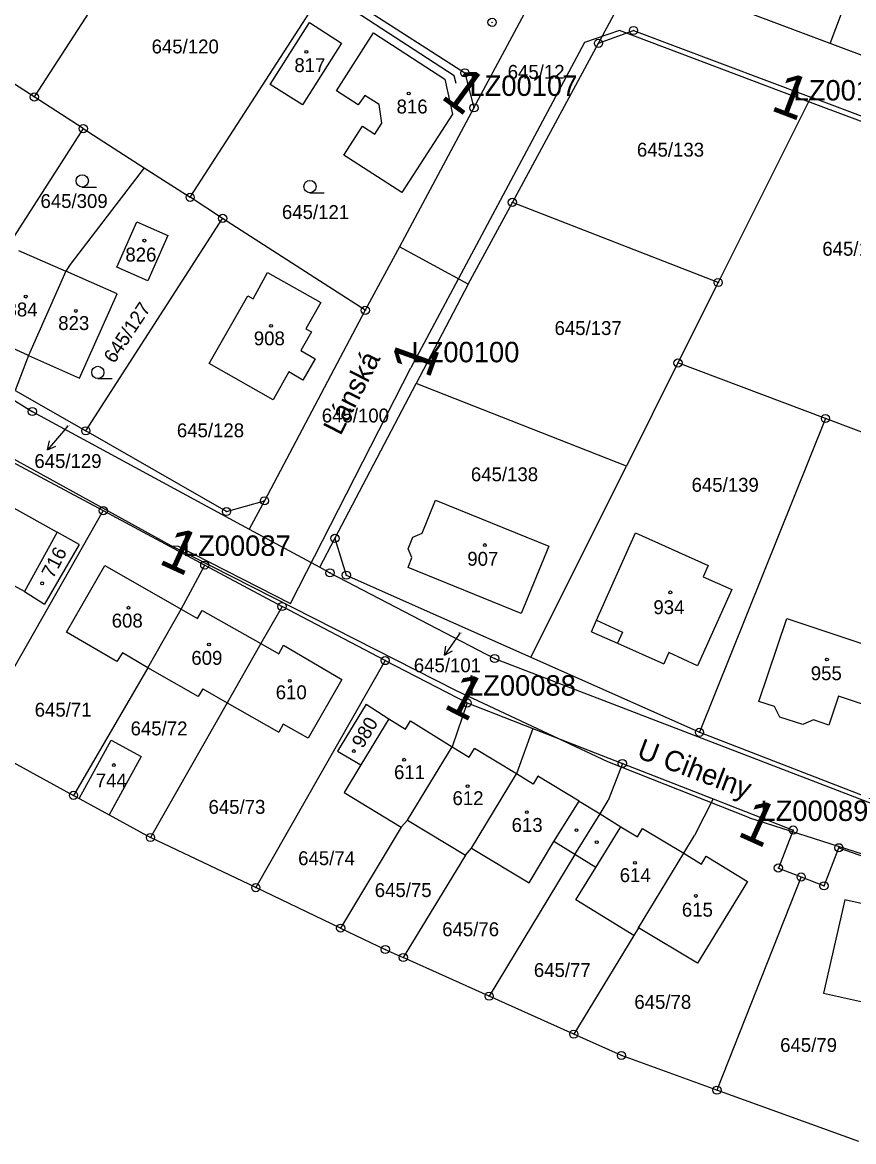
# Model space of a CAD drawing. Extents: x -738131 to -734179, y -1033447 to -1030078.
# Drawn here: x -736106 to -736004.3, y -1032949.2 to -1032812.2 of the extents above; entities that cross this region are included whole.
import ezdxf

# ---------------------------------------------------------------- set-up
doc = ezdxf.new("R2010")
doc.units = 0
for name, color, linetype in [('ftf_2010', 7, 'Continuous'), ('ftf_3010', 7, 'Continuous'), ('ftf_3010_ftf_3010_gtda_3015_gtda_3015_1', 7, 'Continuous'), ('ftf_nu', 7, 'Continuous'), ('Vrstva 1', 7, 'Continuous'), ('Vrstva 2', 7, 'Continuous'), ('Vrstva 3', 7, 'Continuous'), ('Vrstva 4', 7, 'Continuous'), ('Vrstva 5', 7, 'Continuous'), ('Vrstva 7', 7, 'Continuous'), ('Vrstva 8', 7, 'Continuous')]:
    doc.layers.add(name, color=color, linetype=linetype)

msp = doc.modelspace()

# ---------------------------------------------------------------- linework, layer by layer
at = {"layer": 'ftf_2010'}
for points in [[(-736052.9, -1032819.73), (-736053.14, -1032818.79), (-736087.84, -1032796.17)], [(-736013.08, -1032820.73), (-736032.92, -1032813.21), (-736037.22, -1032814.71), (-736058.45, -1032854.48)], [(-735967.72, -1032837.65), (-736013.08, -1032820.73)], [(-736087.78, -1032876.29), (-736086.92, -1032876.31), (-736073.17, -1032883.33), (-736058.45, -1032854.48)], [(-736087.78, -1032876.29), (-736124.23, -1032856.21)], [(-736052.87, -1032894.01), (-736087.78, -1032876.29)], [(-736017.04, -1032909.56), (-736034.36, -1032902.68), (-736052.87, -1032894.01)], [(-736017.04, -1032909.56), (-735980.57, -1032921.21)]]:
    msp.add_lwpolyline(points, dxfattribs=at)
at = {"layer": 'Vrstva 1'}
for points in [[(-736007.17, -1032814.81), (-735995.73, -1032784.44)], [(-736087.69, -1032795.31), (-736104.51, -1032821.36)], [(-736035.51, -1032814.79), (-736029.29, -1032803.29)], [(-736007.17, -1032814.81), (-736027.92, -1032806.99)], [(-736085.44, -1032833.63), (-736068.65, -1032807.58)], [(-736068.65, -1032807.58), (-736051.85, -1032818.41)], [(-736050.74, -1032822.69), (-736044.6, -1032811.22)], [(-736075.67, -1032819.82), (-736070.87, -1032812.24)], [(-736070.87, -1032812.24), (-736066.93, -1032814.79)], [(-736104.51, -1032821.36), (-736115.57, -1032814.24)], [(-736067.55, -1032820.59), (-736063.01, -1032813.53)], [(-736063.01, -1032813.53), (-736054.3, -1032819.17)], [(-736035.51, -1032814.79), (-736031.23, -1032813.23)], [(-736031.23, -1032813.23), (-736009.52, -1032821.4)], [(-736066.93, -1032814.79), (-736071.72, -1032822.32)], [(-736046.04, -1032834.25), (-736035.51, -1032814.79)], [(-735975.92, -1032826.57), (-736007.17, -1032814.81)], [(-736051.85, -1032818.41), (-736050.74, -1032822.69)], [(-736054.3, -1032819.17), (-736053.38, -1032823.45)], [(-736071.72, -1032822.32), (-736075.67, -1032819.82)], [(-736064.88, -1032822.33), (-736067.55, -1032820.59)], [(-736064.1, -1032821.16), (-736064.88, -1032822.33)], [(-736062.35, -1032822.29), (-736064.1, -1032821.16)], [(-736098.52, -1032825.23), (-736104.51, -1032821.36)], [(-736062.01, -1032824.55), (-736062.35, -1032822.29)], [(-736009.52, -1032821.4), (-736020.87, -1032844.06)], [(-735987.42, -1032829.72), (-736009.52, -1032821.4)], [(-736050.74, -1032822.69), (-736059.86, -1032839.69)], [(-736053.38, -1032823.45), (-736059.57, -1032833.03)], [(-736098.52, -1032825.23), (-736115.82, -1032852.13)], [(-736098.52, -1032825.23), (-736091.08, -1032830.01)], [(-736066.64, -1032828.49), (-736064.36, -1032824.93)], [(-736064.36, -1032824.93), (-736062.84, -1032825.91)], [(-736062.84, -1032825.91), (-736062.01, -1032824.55)], [(-736059.57, -1032833.03), (-736066.64, -1032828.49)], [(-736091.08, -1032830.01), (-736100.12, -1032841.87)], [(-736091.08, -1032830.01), (-736085.44, -1032833.63)], [(-736081.47, -1032836.21), (-736085.44, -1032833.63)], [(-736051.45, -1032844.26), (-736046.04, -1032834.25)], [(-736020.87, -1032844.06), (-736046.04, -1032834.25)], [(-736098.21, -1032862.2), (-736081.47, -1032836.21)], [(-736064.03, -1032847.46), (-736081.47, -1032836.21)], [(-736094.4, -1032842.18), (-736091.96, -1032836.65)], [(-736091.96, -1032836.65), (-736088.16, -1032838.32)], [(-736088.16, -1032838.32), (-736090.61, -1032843.84)], [(-736106.46, -1032840.13), (-736100.64, -1032842.69)], [(-736059.86, -1032839.69), (-736064.03, -1032847.46)], [(-736051.45, -1032844.26), (-736059.86, -1032839.69)], [(-736100.64, -1032842.69), (-736105.21, -1032852.97)], [(-736100.12, -1032841.87), (-736100.64, -1032842.69)], [(-736094.37, -1032845.45), (-736100.64, -1032842.69)], [(-736090.61, -1032843.84), (-736094.4, -1032842.18)], [(-736077.74, -1032846.04), (-736075.98, -1032842.83)], [(-736075.98, -1032842.83), (-736069.48, -1032846.49)], [(-736051.45, -1032844.26), (-736057.82, -1032856.43)], [(-736020.87, -1032844.06), (-736025.79, -1032853.9)], [(-736098.97, -1032855.76), (-736094.37, -1032845.45)], [(-736083.12, -1032853.97), (-736078.4, -1032845.67)], [(-736078.4, -1032845.67), (-736077.74, -1032846.04)], [(-736069.48, -1032846.49), (-736071.28, -1032849.72)], [(-736064.03, -1032847.46), (-736076.36, -1032870.76)], [(-736071.28, -1032849.72), (-736070.62, -1032850.11)], [(-736105.21, -1032852.97), (-736111.05, -1032850.35)], [(-736070.62, -1032850.11), (-736071.89, -1032852.38)], [(-736071.89, -1032852.38), (-736070.16, -1032853.39)], [(-736105.21, -1032852.97), (-736106.84, -1032857.26)], [(-736105.21, -1032852.97), (-736098.97, -1032855.76)], [(-736075.29, -1032858.4), (-736083.12, -1032853.97)], [(-736070.16, -1032853.39), (-736071.65, -1032855.99)], [(-736025.79, -1032853.9), (-736032.09, -1032866.51)], [(-736007.75, -1032860.69), (-736025.79, -1032853.9)], [(-736073.38, -1032855), (-736075.29, -1032858.4)], [(-736071.65, -1032855.99), (-736073.38, -1032855)], [(-736067.74, -1032875.36), (-736057.82, -1032856.43)], [(-736032.09, -1032866.51), (-736057.82, -1032856.43)], [(-736107.91, -1032857.89), (-736104.75, -1032859.84)], [(-736106.84, -1032857.26), (-736098.21, -1032862.2)], [(-736104.75, -1032859.84), (-736078.21, -1032874.23)], [(-736007.75, -1032860.69), (-736023.16, -1032899.08)], [(-736000.15, -1032863.54), (-736007.75, -1032860.69)], [(-736081, -1032872.08), (-736098.21, -1032862.2)], [(-736108.53, -1032865.3), (-736096.07, -1032871.97)], [(-736043.8, -1032889.9), (-736032.09, -1032866.51)], [(-736110.87, -1032869.49), (-736101.71, -1032874.62)], [(-736081, -1032872.08), (-736076.36, -1032870.76)], [(-736076.36, -1032870.76), (-736078.21, -1032874.23)], [(-736057.09, -1032874.72), (-736055.42, -1032870.7)], [(-736055.42, -1032870.7), (-736041.59, -1032876.3)], [(-736096.07, -1032871.97), (-736112.08, -1032900.05)], [(-736096.07, -1032871.97), (-736083.66, -1032878.63)], [(-736078.21, -1032874.23), (-736069.59, -1032878.9)], [(-736101.71, -1032874.62), (-736105.71, -1032881.85)], [(-736099.01, -1032876.13), (-736101.71, -1032874.62)], [(-736069.59, -1032878.9), (-736067.74, -1032875.36)], [(-736067.74, -1032875.36), (-736066.35, -1032879.86)], [(-736058.79, -1032876.62), (-736058.21, -1032875.2)], [(-736058.21, -1032875.2), (-736057.09, -1032874.72)], [(-736035.77, -1032885.38), (-736030.98, -1032874.68)], [(-736030.98, -1032874.68), (-736022.1, -1032878.68)], [(-736099.01, -1032876.13), (-736103.26, -1032883.39)], [(-736058.33, -1032877.72), (-736058.79, -1032876.62)], [(-736041.59, -1032876.3), (-736044.96, -1032884.56)], [(-736086.54, -1032884.01), (-736083.66, -1032878.63)], [(-736083.66, -1032878.63), (-736074.21, -1032883.7)], [(-736058.8, -1032878.91), (-736058.33, -1032877.72)], [(-736100.56, -1032886.84), (-736095.88, -1032878.69)], [(-736095.88, -1032878.69), (-736086.54, -1032884.01)], [(-736069.59, -1032878.9), (-736068.35, -1032879.57)], [(-736068.35, -1032879.57), (-736048.21, -1032890.05)], [(-736066.35, -1032879.86), (-736043.8, -1032889.9)], [(-736044.96, -1032884.56), (-736058.8, -1032878.91)], [(-736022.1, -1032878.68), (-736022.71, -1032880.05)], [(-736105.71, -1032881.85), (-736108.69, -1032880.22)], [(-736022.71, -1032880.05), (-736019.19, -1032881.63)], [(-736105.71, -1032881.85), (-736103.26, -1032883.39)], [(-736019.19, -1032881.63), (-736023.38, -1032890.96)], [(-736090.61, -1032891.19), (-736086.54, -1032884.01)], [(-736074.21, -1032883.7), (-736076.79, -1032888.24)], [(-736061.59, -1032890.31), (-736074.21, -1032883.7)], [(-736036.37, -1032886.78), (-736035.77, -1032885.38)], [(-736015.88, -1032895.3), (-736012.46, -1032885.17)], [(-736012.46, -1032885.17), (-735998.42, -1032889.85)], [(-736094.42, -1032890.41), (-736100.56, -1032886.84)], [(-736036.37, -1032886.78), (-736033.2, -1032888.19)], [(-736076.79, -1032888.24), (-736080.9, -1032895.46)], [(-736076.79, -1032888.24), (-736074.61, -1032889.47)], [(-736033.2, -1032888.19), (-736027.53, -1032890.71)], [(-736093.72, -1032889.38), (-736094.42, -1032890.41)], [(-736090.61, -1032891.19), (-736093.72, -1032889.38)], [(-736074.61, -1032889.47), (-736074.02, -1032888.44)], [(-736074.02, -1032888.44), (-736066.91, -1032892.61)], [(-736026.9, -1032889.34), (-736027.53, -1032890.71)], [(-736023.38, -1032890.96), (-736026.9, -1032889.34)], [(-736061.59, -1032890.31), (-736077.42, -1032918.09)], [(-736061.59, -1032890.31), (-736051.57, -1032895.5)], [(-736048.21, -1032890.05), (-735998.04, -1032909.35)], [(-736043.8, -1032889.9), (-736023.16, -1032899.08)], [(-736090.61, -1032891.19), (-736099.72, -1032906.8)], [(-736084.47, -1032894.69), (-736090.61, -1032891.19)], [(-736066.91, -1032892.61), (-736071.01, -1032899.8)], [(-736083.89, -1032893.75), (-736084.47, -1032894.69)], [(-736083.89, -1032893.75), (-736080.9, -1032895.46)], [(-736006.15, -1032894.67), (-736007.32, -1032898.22)], [(-736000.64, -1032896.5), (-736006.15, -1032894.67)], [(-736080.9, -1032895.46), (-736090.29, -1032911.95)], [(-736080.9, -1032895.46), (-736074.61, -1032899.07)], [(-736063.9, -1032895.64), (-736067.41, -1032901.41)], [(-736063.9, -1032895.64), (-736061.15, -1032897.43)], [(-736051.57, -1032895.5), (-736053.4, -1032900.85)], [(-736051.57, -1032895.5), (-736043.53, -1032898.63)], [(-736013.98, -1032895.94), (-736015.88, -1032895.3)], [(-736013.33, -1032897.24), (-736013.98, -1032895.94)], [(-736061.15, -1032897.43), (-736064.56, -1032903.05)], [(-736061.15, -1032897.43), (-736059.12, -1032898.69)], [(-736059.12, -1032898.69), (-736058.48, -1032897.67)], [(-736058.48, -1032897.67), (-736053.4, -1032900.85)], [(-736010.5, -1032898.14), (-736013.33, -1032897.24)], [(-736009.22, -1032897.55), (-736010.5, -1032898.14)], [(-736007.32, -1032898.22), (-736009.22, -1032897.55)], [(-736074.09, -1032898.08), (-736074.61, -1032899.07)], [(-736071.01, -1032899.8), (-736074.09, -1032898.08)], [(-736043.53, -1032898.63), (-736045.55, -1032904.17)], [(-736043.53, -1032898.63), (-736032.58, -1032902.9)], [(-736023.16, -1032899.08), (-736001.98, -1032907.27)], [(-736112.08, -1032900.05), (-736099.72, -1032906.8)], [(-736099.02, -1032907.18), (-736095.11, -1032900.03)], [(-736095.11, -1032900.03), (-736091.45, -1032902.04)], [(-736067.41, -1032901.41), (-736064.56, -1032903.05)], [(-736058.85, -1032909.84), (-736053.4, -1032900.85)], [(-736091.45, -1032902.04), (-736095.36, -1032909.18)], [(-736064.56, -1032903.05), (-736066.63, -1032906.47)], [(-736032.58, -1032902.9), (-736034.34, -1032907.44)], [(-736032.58, -1032902.9), (-736021.48, -1032907.22)], [(-736051.02, -1032913.24), (-736045.55, -1032904.17)], [(-736099.72, -1032906.8), (-736099.02, -1032907.18)], [(-736099.02, -1032907.18), (-736095.36, -1032909.18)], [(-736066.63, -1032906.47), (-736059.62, -1032910.71)], [(-736021.48, -1032907.22), (-736023.75, -1032911.7)], [(-736021.48, -1032907.22), (-736011.7, -1032911.04)], [(-736035.32, -1032909.08), (-736034.34, -1032907.44)], [(-736095.36, -1032909.18), (-736090.29, -1032911.95)], [(-736058.85, -1032909.84), (-736059.62, -1032910.71)], [(-736058.85, -1032909.84), (-736051.78, -1032914.1)], [(-736038.4, -1032914.03), (-736035.32, -1032909.08)], [(-736059.62, -1032910.71), (-736067.04, -1032923.04)], [(-736011.7, -1032911.04), (-736013.51, -1032915.69)], [(-736077.42, -1032918.09), (-736090.29, -1032911.95)], [(-736043.98, -1032917.5), (-736040.96, -1032912.44)], [(-736038.4, -1032914.03), (-736040.96, -1032912.44)], [(-736025.08, -1032913.87), (-736023.75, -1032911.7)], [(-736051.78, -1032914.1), (-736059.38, -1032926.64)], [(-736051.78, -1032914.1), (-736051.02, -1032913.24)], [(-736051.02, -1032913.24), (-736043.98, -1032917.5)], [(-736038.4, -1032914.03), (-736048.88, -1032931.36)], [(-736035.83, -1032915.62), (-736038.4, -1032914.03)], [(-736030.6, -1032923.02), (-736025.08, -1032913.87)], [(-736025.08, -1032913.87), (-736022.91, -1032915.22)], [(-736022.91, -1032915.22), (-736022.32, -1032914.24)], [(-736022.32, -1032914.24), (-736017.27, -1032917.32)], [(-736007.92, -1032917.87), (-736006.11, -1032913.21)], [(-736006.11, -1032913.21), (-735996.2, -1032916.69)], [(-736038.29, -1032919.6), (-736035.83, -1032915.62)], [(-736010.72, -1032916.78), (-736021.02, -1032942.86)], [(-736013.51, -1032915.69), (-736010.72, -1032916.78)], [(-736010.72, -1032916.78), (-736007.92, -1032917.87)], [(-736067.04, -1032923.04), (-736077.42, -1032918.09)], [(-736017.27, -1032917.32), (-736023.4, -1032927.32)], [(-736031.19, -1032923.94), (-736038.29, -1032919.6)], [(-736005.37, -1032919.59), (-736007.98, -1032930.98)], [(-735997.35, -1032921.38), (-736005.37, -1032919.59)], [(-736067.04, -1032923.04), (-736061.58, -1032925.65)], [(-736030.6, -1032923.02), (-736031.19, -1032923.94)], [(-736023.4, -1032927.32), (-736030.6, -1032923.02)], [(-736031.19, -1032923.94), (-736038.52, -1032936.01)], [(-736061.58, -1032925.65), (-736059.38, -1032926.64)], [(-736048.88, -1032931.36), (-736059.38, -1032926.64)], [(-736038.52, -1032936.01), (-736048.88, -1032931.36)], [(-736007.98, -1032930.98), (-735999.92, -1032932.81)], [(-736032.7, -1032938.62), (-736038.52, -1032936.01)], [(-736021.02, -1032942.86), (-736032.7, -1032938.62)], [(-736003.65, -1032949.16), (-736021.02, -1032942.86)]]:
    msp.add_lwpolyline(points, dxfattribs=at)
at = {"layer": 'Vrstva 3'}
for p, q in [((-736098.64, -1032832.38), (-736096.89, -1032832.38)), ((-736070.79, -1032833.08), (-736069.04, -1032833.08)), ((-736096.74, -1032855.8), (-736094.99, -1032855.8))]:
    msp.add_line(p, q, dxfattribs=at)
for centre in [(-736098.64, -1032831.63), (-736070.79, -1032832.33), (-736096.74, -1032855.05)]:
    msp.add_circle(centre, 0.75, dxfattribs=at)
at = {"layer": 'Vrstva 4'}
for points in [[(-736086.54, -1032884.01), (-736084.53, -1032885.17)], [(-736084.53, -1032885.17), (-736083.97, -1032884.18)], [(-736083.97, -1032884.18), (-736076.79, -1032888.24)], [(-736035.77, -1032885.38), (-736032.58, -1032886.83)], [(-736032.58, -1032886.83), (-736033.2, -1032888.19)], [(-736053.4, -1032900.85), (-736051.34, -1032902.13)], [(-736051.34, -1032902.13), (-736050.67, -1032901.07)], [(-736045.55, -1032904.17), (-736050.67, -1032901.07)], [(-736043.5, -1032905.41), (-736045.55, -1032904.17)], [(-736042.91, -1032904.44), (-736043.5, -1032905.41)], [(-736037.86, -1032907.51), (-736042.91, -1032904.44)], [(-736040.96, -1032912.44), (-736037.86, -1032907.51)], [(-736037.86, -1032907.51), (-736035.32, -1032909.08)], [(-736035.32, -1032909.08), (-736032.78, -1032910.66)], [(-736035.83, -1032915.62), (-736032.78, -1032910.66)], [(-736032.78, -1032910.66), (-736030.73, -1032911.89)], [(-736030.73, -1032911.89), (-736030.11, -1032910.86)], [(-736030.11, -1032910.86), (-736025.08, -1032913.87)]]:
    msp.add_lwpolyline(points, dxfattribs=at)
at = {"layer": 'Vrstva 5'}
for centre in [(-736071.23, -1032815.84), (-736058.72, -1032820.93), (-736091.04, -1032838.93), (-736105.56, -1032845.78), (-736099.43, -1032847.54), (-736075.55, -1032849.35), (-736049.41, -1032876.18), (-736103.55, -1032880.86), (-736026.72, -1032881.97), (-736092.98, -1032883.84), (-736083.15, -1032888.34), (-736007.56, -1032890.18), (-736073.26, -1032892.79), (-736065.42, -1032901.38), (-736094.78, -1032903.09), (-736059.29, -1032902.44), (-736051.51, -1032905.68), (-736044.27, -1032908.85), (-736038.19, -1032911.05), (-736035.72, -1032912.53), (-736031.05, -1032915.05), (-736023.6, -1032919.1)]:
    msp.add_circle(centre, 0.175, dxfattribs=at)
at = {"layer": 'Vrstva 7'}
for p, q in [((-736100.95, -1032862.23), (-736102.91, -1032864.51)), ((-736102.91, -1032864.51), (-736102.63, -1032863.42)), ((-736102.91, -1032864.51), (-736101.87, -1032864.07)), ((-736052.63, -1032887.2), (-736054.35, -1032889.66)), ((-736054.35, -1032889.66), (-736054.19, -1032888.55)), ((-736054.35, -1032889.66), (-736053.37, -1032889.12))]:
    msp.add_line(p, q, dxfattribs=at)
for points in [[(-736100.41, -1032861.61), (-736100.95, -1032862.23)], [(-736052.46, -1032886.96), (-736052.63, -1032887.2)]]:
    msp.add_lwpolyline(points, dxfattribs=at)
at = {"layer": 'Vrstva 8'}
for centre, radius in [((-736048.52, -1032812.23), 0.5), ((-736048.52, -1032812.23), 0.0303), ((-736031.23, -1032813.23), 0.5), ((-736035.51, -1032814.79), 0.5), ((-736031.23, -1032813.23), 0.0303), ((-736035.51, -1032814.79), 0.0303), ((-736051.85, -1032818.41), 0.5), ((-736051.85, -1032818.41), 0.0303), ((-736104.51, -1032821.36), 0.5), ((-736104.51, -1032821.36), 0.0303), ((-736050.74, -1032822.69), 0.5), ((-736050.74, -1032822.69), 0.0303), ((-736098.52, -1032825.23), 0.5), ((-736098.52, -1032825.23), 0.0303), ((-736085.44, -1032833.63), 0.5), ((-736085.44, -1032833.63), 0.0303), ((-736046.04, -1032834.25), 0.5), ((-736046.04, -1032834.25), 0.0303), ((-736081.47, -1032836.21), 0.5), ((-736081.47, -1032836.21), 0.0303), ((-736020.87, -1032844.06), 0.5), ((-736020.87, -1032844.06), 0.0303), ((-736064.03, -1032847.46), 0.5), ((-736064.03, -1032847.46), 0.0303), ((-736025.79, -1032853.9), 0.5), ((-736025.79, -1032853.9), 0.0303), ((-736104.75, -1032859.84), 0.5), ((-736104.75, -1032859.84), 0.0303), ((-736007.75, -1032860.69), 0.5), ((-736007.75, -1032860.69), 0.0303), ((-736098.21, -1032862.2), 0.5), ((-736098.21, -1032862.2), 0.0303), ((-736076.36, -1032870.76), 0.5), ((-736096.07, -1032871.97), 0.5), ((-736081, -1032872.08), 0.5), ((-736076.36, -1032870.76), 0.0303), ((-736096.07, -1032871.97), 0.0303), ((-736081, -1032872.08), 0.0303), ((-736067.74, -1032875.36), 0.5), ((-736067.74, -1032875.36), 0.0303), ((-736083.66, -1032878.63), 0.5), ((-736083.66, -1032878.63), 0.0303), ((-736068.35, -1032879.57), 0.5), ((-736068.35, -1032879.57), 0.0303), ((-736066.35, -1032879.86), 0.5), ((-736066.35, -1032879.86), 0.0303), ((-736074.21, -1032883.7), 0.5), ((-736074.21, -1032883.7), 0.0303), ((-736048.21, -1032890.05), 0.5), ((-736061.59, -1032890.31), 0.5), ((-736061.59, -1032890.31), 0.0303), ((-736048.21, -1032890.05), 0.0303), ((-736051.57, -1032895.5), 0.5), ((-736051.57, -1032895.5), 0.0303), ((-736023.16, -1032899.08), 0.5), ((-736023.16, -1032899.08), 0.0303), ((-736032.58, -1032902.9), 0.5), ((-736032.58, -1032902.9), 0.0303), ((-736099.72, -1032906.8), 0.5), ((-736099.72, -1032906.8), 0.0303), ((-736090.29, -1032911.95), 0.5), ((-736011.7, -1032911.04), 0.5), ((-736011.7, -1032911.04), 0.0303), ((-736090.29, -1032911.95), 0.0303), ((-736006.11, -1032913.21), 0.5), ((-736006.11, -1032913.21), 0.0303), ((-736013.51, -1032915.69), 0.5), ((-736013.51, -1032915.69), 0.0303), ((-736010.72, -1032916.78), 0.5), ((-736010.72, -1032916.78), 0.0303), ((-736077.42, -1032918.09), 0.5), ((-736077.42, -1032918.09), 0.0303), ((-736007.92, -1032917.87), 0.5), ((-736007.92, -1032917.87), 0.0303), ((-736067.04, -1032923.04), 0.5), ((-736067.04, -1032923.04), 0.0303), ((-736061.58, -1032925.65), 0.5), ((-736061.58, -1032925.65), 0.0303), ((-736059.38, -1032926.64), 0.5), ((-736059.38, -1032926.64), 0.0303), ((-736048.88, -1032931.36), 0.5), ((-736048.88, -1032931.36), 0.0303), ((-736038.52, -1032936.01), 0.5), ((-736038.52, -1032936.01), 0.0303), ((-736032.7, -1032938.62), 0.5), ((-736032.7, -1032938.62), 0.0303), ((-736021.02, -1032942.86), 0.5), ((-736021.02, -1032942.86), 0.0303)]:
    msp.add_circle(centre, radius, dxfattribs=at)

# ---------------------------------------------------------------- texts
at = {"layer": 'ftf_3010'}
for rotation, p in [(323.6455, (-736054.96, -1032821.44)), (339.1572, (-736014.61, -1032822.93)), (70.2215, (-736056.22, -1032855.97)), (335.4521, (-736089.45, -1032878.38)), (333.0089, (-736054.63, -1032896.04)), (335.7622, (-736018.7, -1032911.67))]:
    msp.add_text('1', height=5.2, rotation=rotation, dxfattribs=at).set_placement(p)
at = {"layer": 'ftf_3010_ftf_3010_gtda_3015_gtda_3015_1'}
for s, p in [('LZ00107', (-736051.29, -1032821.23)), ('LZ00101', (-736011.65, -1032821.79)), ('LZ00087', (-736086.34, -1032877.5)), ('LZ00088', (-736051.47, -1032894.6)), ('LZ00089', (-736015.7, -1032909.93))]:
    msp.add_text(s, height=2.5, dxfattribs=at).set_placement(p)
msp.add_text('LZ00100', height=2.5, rotation=0, dxfattribs=at).set_placement((-736058.38, -1032853.82))
at = {"layer": 'ftf_nu'}
for s, rotation, p in [('Lánská', 62.7435, (-736067.06, -1032862.89)), ('U Cihelny', 339.213, (-736030.95, -1032902.14))]:
    msp.add_text(s, height=2.5, rotation=rotation, dxfattribs=at).set_placement(p)
at = {"layer": 'Vrstva 2'}
for s, height, p in [('645/120', 1.7, (-736090.16, -1032816.03)), ('817', 1.7, (-736072.7, -1032818.32)), ('645/12', 1.7, (-736046.61, -1032819.14)), ('816', 1.7, (-736060.2, -1032823.38)), ('645/133', 1.7, (-736030.81, -1032828.66)), ('645/309', 1.7, (-736103.75, -1032834.94)), ('645/121', 1.7, (-736074.22, -1032836.29)), ('826', 1.7, (-736093.37, -1032841.49)), ('645/134', 1.7, (-736008.13, -1032840.78)), ('884', 1.7, (-736107.9, -1032848.21)), ('823', 1.7, (-736101.58, -1032849.87)), ('645/137', 1.7, (-736040.88, -1032850.48)), ('908', 1.7, (-736077.66, -1032851.74)), ('645/100', 1.7, (-736069.35, -1032861.18)), ('645/129', 0.1, (-736100.65, -1032861.61)), ('645/128', 1.7, (-736087.07, -1032862.99)), ('645/138', 1.7, (-736051.11, -1032868.37)), ('645/139', 1.7, (-736024.12, -1032869.66)), ('907', 1.7, (-736051.55, -1032878.71)), ('934', 1.7, (-736028.79, -1032884.63)), ('608', 1.7, (-736095.04, -1032886.27)), ('645/101', 0.1, (-736052.68, -1032886.96)), ('609', 1.7, (-736085.3, -1032890.83)), ('955', 1.7, (-736009.54, -1032892.71)), ('610', 1.7, (-736074.98, -1032895.04)), ('645/71', 1.7, (-736104.46, -1032897.17)), ('645/72', 1.7, (-736092.73, -1032899.46)), ('611', 1.7, (-736060.51, -1032904.81)), ('744', 1.7, (-736096.99, -1032905.83)), ('645/73', 1.7, (-736083.2, -1032909.06)), ('612', 1.7, (-736053.36, -1032907.99)), ('613', 1.7, (-736046.13, -1032911.27)), ('645/74', 1.7, (-736072.24, -1032915.34)), ('614', 1.7, (-736032.91, -1032917.41)), ('645/75', 1.7, (-736062.87, -1032919.24)), ('615', 1.7, (-736025.31, -1032921.64)), ('645/76', 1.7, (-736054.62, -1032924.03)), ('645/77', 1.7, (-736043.41, -1032929.02)), ('645/78', 1.7, (-736031.12, -1032932.92)), ('645/79', 1.7, (-736013.29, -1032938.19))]:
    msp.add_text(s, height=height, dxfattribs=at).set_placement(p)
for s, rotation, p in [('645/127', 56.358, (-736094.73, -1032854.06)), ('716', 62.6007, (-736102.21, -1032880.36)), ('980', 59.3354, (-736064.33, -1032901.15))]:
    msp.add_text(s, height=1.7, rotation=rotation, dxfattribs=at).set_placement(p)
at = {"layer": 'Vrstva 7'}
for s, p in [('645/129', (-736104.5, -1032866.75)), ('645/101', (-736058.09, -1032891.74))]:
    msp.add_text(s, height=1.7, dxfattribs=at).set_placement(p)

doc.saveas('drawing.dxf')
